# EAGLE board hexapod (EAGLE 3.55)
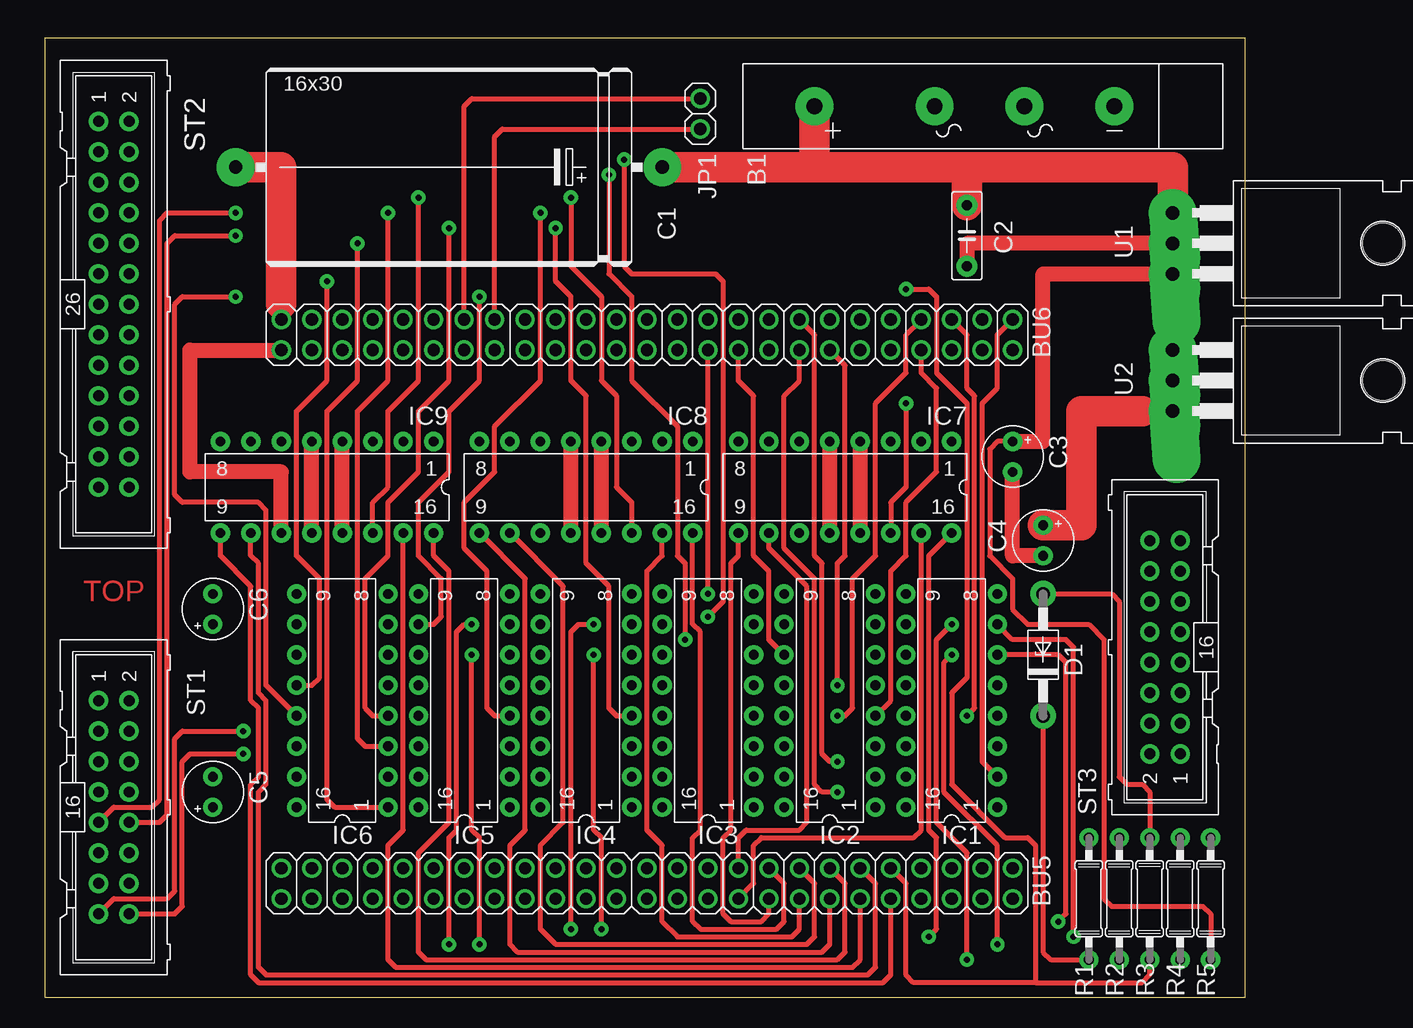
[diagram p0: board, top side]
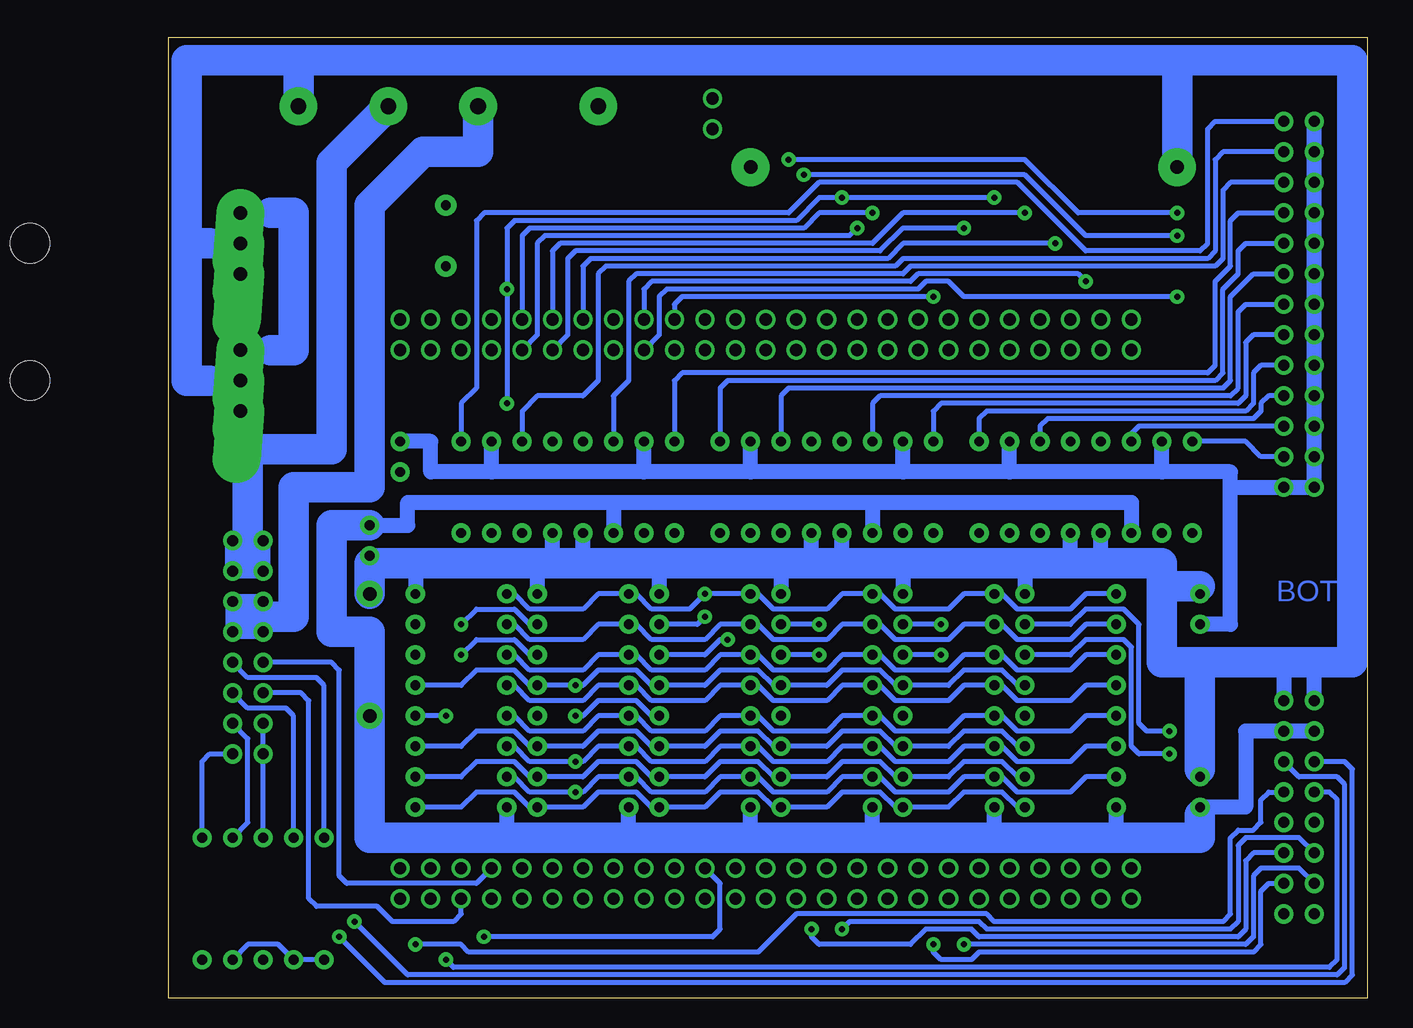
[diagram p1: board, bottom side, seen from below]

Size 100 x 80 mm. Coordinates in mm from the lower left corner, seen from the top.
Outline: 0,0 0,80 100,80 100,0 0,0
Copper layers used: Top, Bottom

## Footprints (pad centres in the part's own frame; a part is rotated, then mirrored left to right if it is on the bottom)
100 = drill 1.321 pad 3.15 round:  0,0;  10.008,0;  17.501,0;  24.994,0
25 = drill 1.016 pad 1.6 round:  -30.48,-1.27;  -30.48,1.27;  -27.94,-1.27;  -27.94,1.27;  -25.4,-1.27;  -25.4,1.27;  -22.86,-1.27;  -22.86,1.27;  -20.32,-1.27;  -20.32,1.27;  -17.78,-1.27;  -17.78,1.27;  -15.24,-1.27;  -15.24,1.27;  -12.7,-1.27;  -12.7,1.27;  -10.16,-1.27;  -10.16,1.27;  -7.62,-1.27;  -7.62,1.27;  -5.08,-1.27;  -5.08,1.27;  -2.54,-1.27;  -2.54,1.27;  0,-1.27;  0,1.27;  2.54,-1.27;  2.54,1.27;  5.08,-1.27;  5.08,1.27;  7.62,-1.27;  7.62,1.27;  10.16,-1.27;  10.16,1.27;  12.7,-1.27;  12.7,1.27;  15.24,-1.27;  15.24,1.27;  17.78,-1.27;  17.78,1.27;  20.32,1.27;  20.32,-1.27;  22.86,-1.27;  25.4,-1.27;  27.94,-1.27;  27.94,1.27;  25.4,1.27;  22.86,1.27;  30.48,1.27;  30.48,-1.27
5-16 = drill 1.118 pad 3.15 round:  -17.78,0;  17.78,0
B2,5A = drill 0.813 pad 1.778 round:  -2.54,0;  2.54,0
,5-5 = drill 0.813 pad 1.6 round:  1.27,0;  -1.27,0
41Z10 = drill 1.118 pad 2.159 round:  -5.08,0;  5.08,0
L-16 = drill 0.813 pad 1.6 round:  -8.89,-3.81;  -6.35,-3.81;  -3.81,-3.81;  -1.27,-3.81;  1.27,-3.81;  3.81,-3.81;  6.35,-3.81;  8.89,-3.81;  8.89,3.81;  6.35,3.81;  3.81,3.81;  1.27,3.81;  -1.27,3.81;  -3.81,3.81;  -6.35,3.81;  -8.89,3.81
02 = drill 1.016 pad 1.6 round:  -1.27,0;  1.27,0
07/10 = drill 0.813 pad 1.6 round:  -5.08,0;  5.08,0
16 = drill 0.914 pad 1.6 round:  -8.89,-1.27;  -8.89,1.27;  -6.35,-1.27;  -6.35,1.27;  -3.81,-1.27;  -3.81,1.27;  -1.27,-1.27;  -1.27,1.27;  1.27,-1.27;  1.27,1.27;  3.81,-1.27;  3.81,1.27;  6.35,-1.27;  6.35,1.27;  8.89,-1.27;  8.89,1.27
26 = drill 0.914 pad 1.6 round:  -15.24,-1.27;  -15.24,1.27;  -12.7,-1.27;  -12.7,1.27;  -10.16,-1.27;  -10.16,1.27;  -7.62,-1.27;  -7.62,1.27;  -5.08,-1.27;  -5.08,1.27;  -2.54,-1.27;  -2.54,1.27;  0,-1.27;  0,1.27;  2.54,-1.27;  2.54,1.27;  5.08,-1.27;  5.08,1.27;  7.62,-1.27;  7.62,1.27;  10.16,-1.27;  10.16,1.27;  12.7,-1.27;  12.7,1.27;  15.24,-1.27;  15.24,1.27
220H = drill 1.118 pad 4 offset:  -2.54,-6.35;  0,-6.35;  2.54,-6.35 | hole 3.302: 0,11.176

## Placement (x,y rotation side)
B1  FB100  [100]  64.14,74.3 0 top
BU5  PINHD-2X25  [25]  50.16,9.53 180 top
BU6  PINHD-2X25  [25]  50.16,55.24 180 top
C1  2200uF/35V  [5-16]  33.66,69.22 180 top
C2  100nf  [B2,5A]  76.83,63.5 90 top
C3  4,7uf/35V  [,5-5]  80.64,45.09 270 top
C4  4,7uf/10V  [,5-5]  83.19,38.1 270 top
C5  4,7uf/10V  [,5-5]  13.97,17.14 90 top
C6  4,7uf/35V  [,5-5]  13.97,32.38 90 top
D1  BZX85  [41Z10]  83.19,28.57 90 top
IC1  HCTL2016  [L-16]  75.56,24.77 90 top
IC2  HCTL2016  [L-16]  65.41,24.77 90 top
IC3  HCTL2016  [L-16]  55.24,24.77 90 top
IC4  HCTL2016  [L-16]  45.09,24.77 90 top
IC5  HCTL2016  [L-16]  34.92,24.77 90 top
IC6  HCTL2016  [L-16]  24.77,24.77 90 top
IC7  DS3668  [L-16]  66.67,42.55 180 top
IC8  DS3668  [L-16]  45.09,42.55 180 top
IC9  DS3668  [L-16]  23.5,42.55 180 top
JP1  PINHD-1X2  [02]  54.61,73.66 270 top
R1  0207/10  [07/10]  87,8.26 90 top
R2  0207/10  [07/10]  89.53,8.26 90 top
R3  10k  [07/10]  92.08,8.26 270 top
R4  0207/10  [07/10]  94.61,8.26 90 top
R5  0207/10  [07/10]  97.16,8.26 90 top
ST1  PINHD-2X8  [16]  5.71,15.88 270 top
ST2  PINHD-2X13  [26]  5.71,57.78 270 top
ST3  PINHD-2X8  [16]  93.34,29.21 90 top
U1  78S24  [220H]  100.33,62.87 270 top
U2  7805  [220H]  100.33,51.44 270 top

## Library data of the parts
B1 = RECTIF
BU5 BU6 JP1 = PINHEAD
C1 C3-C6 = ELKO
C2 = CAP-WI
D1 = diode
IC1-IC9 = klaus
R1-R5 = R
ST1-ST3 = ST-ML
U1 U2 = LINEAR

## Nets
+5V: BU6. C4. C5. D1. IC1. IC2. IC3. IC4. IC5. IC6. IC7. IC8. IC9. R1. R2. R4. ST1. U2.
+24V: C3. C6. IC7. IC8. IC9. R5. ST2. U1.
AC1: B1. ST3.
AC2: B1. ST3.
CLK: BU6. IC1. IC2. IC3. IC4. IC5. IC6.
COIL0: IC7. ST2.
COIL1: IC7. ST2.
COIL2: IC7. ST2.
COIL3: IC7. ST2.
COIL4: IC8. ST2.
COIL5: IC8. ST2.
COIL6: IC8. ST2.
COIL7: IC8. ST2.
COIL8: IC9. ST2.
COIL9: IC9. ST2.
COIL10: IC9. ST2.
COIL11: IC9. ST2.
D0: BU6. IC1. IC2. IC3. IC4. IC5. IC6.
D1: BU6. IC1. IC2. IC3. IC4. IC5. IC6.
D2: BU6. IC1. IC2. IC3. IC4. IC5. IC6.
D3: BU6. IC1. IC2. IC3. IC4. IC5. IC6.
D4: BU6. IC1. IC2. IC3. IC4. IC5. IC6.
D5: BU6. IC1. IC2. IC3. IC4. IC5. IC6.
D6: BU6. IC1. IC2. IC3. IC4. IC5. IC6.
D7: BU6. IC1. IC2. IC3. IC4. IC5. IC6.
EN: BU5. IC7. IC8. IC9. R3.
ENC0: IC1. ST1.
ENC1: IC1. ST1.
ENC2: IC2. ST1.
ENC3: IC2. ST1.
ENC4: IC3. ST1.
ENC5: IC3. ST1.
ENC6: IC4. ST1.
ENC7: IC4. ST1.
ENC8: IC5. ST1.
ENC9: IC5. ST1.
ENC10: IC6. ST1.
ENC11: IC6. ST1.
GND: B1. BU6. C1. C2. C3. C4. C5. C6. D1. IC1. IC2. IC3. IC4. IC5. IC6. IC7. IC8. IC9. R3. ST1. ST3. U1. U2.
N$4: R5. ST3.
N$5: R4. ST3.
N$6: R2. ST3.
N$7: R1. ST3.
N$8: BU6. JP1.
N$9: BU6. JP1.
OE\0: BU6. IC1.
OE\1: BU6. IC2.
OE\2: BU6. IC3.
OE\3: BU6. IC4.
OE\4: BU6. IC5.
OE\5: BU6. IC6.
RST\: BU6. IC1. IC2. IC3. IC4. IC5. IC6.
SEL: BU6. IC1. IC2. IC3. IC4. IC5. IC6.
STATUS0: BU5. ST3.
STATUS1: BU5. ST3.
VALVE0: BU5. IC7.
VALVE1: BU5. IC7.
VALVE2: BU5. IC7.
VALVE3: BU5. IC7.
VALVE4: BU5. IC8.
VALVE5: BU5. IC8.
VALVE6: BU5. IC8.
VALVE7: BU5. IC8.
VALVE8: BU5. IC9.
VALVE9: BU5. IC9.
VALVE10: BU5. IC9.
VALVE11: BU5. IC9.
VIN: B1. C1. C2. U1. U2.

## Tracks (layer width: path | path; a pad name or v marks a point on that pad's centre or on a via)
+5V
  Top 0.406: 87,3.17 83.82,3.17 83.19,3.81 83.19,23.5
  Top 1.27: 19.68,53.98 12.06,53.98 12.06,43.81 19.68,43.81 19.68,38.73 | 91.44,48.9 U2.
  Top 2.54: C4. 86.36,39.37 86.36,48.9 91.44,48.9
  Bottom 0.406: 87,3.17 89.53,3.17 90.81,4.45 93.34,4.45 94.61,3.17
  Bottom 1.27: 20.95,13.34 IC6. | 31.11,13.34 IC5. | 41.27,13.34 IC4. | 51.44,13.34 IC3. | 61.59,13.34 IC2. | 71.75,13.34 IC1. | 19.68,38.73 19.68,41.27 41.27,41.27 | 62.87,41.27 41.27,41.27 | 41.27,41.27 41.27,38.73 | 62.87,41.27 62.87,38.73 | 62.87,41.27 80.01,41.27 80.01,39.37 C4. | 13.97,15.24 C5. 10.16,15.88 10.16,22.23 6.99,22.23 4.45,22.23
  Bottom 2.54: C4. 86.36,39.37 86.36,30.48 83.19,30.48 83.19,23.5 83.19,13.34 71.75,13.34 61.59,13.34 51.44,13.34 41.27,13.34 31.11,13.34 20.95,13.34 13.97,13.34 13.97,15.24
+24V
  Top 0.406: 97.16,3.17 97.16,6.99 96.52,7.62 88.9,7.62 88.27,8.26 88.27,29.84 87,31.11 81.92,31.11 80.64,32.38 80.64,34.92 78.74,36.83 78.74,45.72 79.38,46.35 C3.
  Top 1.27: C3. 83.19,46.35 83.19,60.33 U1.
  Bottom 1.27: 17.14,43.81 17.14,46.35 | C3. 78.11,46.35 78.11,43.81 73.03,43.81 | 60.33,43.81 73.03,43.81 | 51.44,43.81 60.33,43.81 | 38.73,43.81 51.44,43.81 | 29.84,43.81 38.73,43.81 | 17.14,43.81 29.84,43.81 | 29.84,43.81 29.84,46.35 | 38.73,43.81 38.73,46.35 | 51.44,43.81 51.44,46.35 | 60.33,43.81 60.33,46.35 | 73.03,43.81 73.03,46.35 | 17.14,43.81 11.43,43.81 11.43,42.55 | 11.43,42.55 ST2. 4.45,42.55 4.45,45.09 4.45,47.62 4.45,50.16 4.45,52.7 4.45,55.24 4.45,57.78 4.45,60.33 4.45,62.87 4.45,65.41 4.45,67.94 4.45,70.48 4.45,73.03 | 11.43,42.55 11.43,31.11 C6.
AC1
  Bottom 1.27: 92.08,30.48 94.61,30.48 94.61,33.02 92.08,33.02 92.08,31.75 92.08,30.48
  Bottom 1.524: 92.08,30.48 94.61,33.02 | 92.08,33.02 94.61,30.48
  Bottom 2.54: 74.14,74.3 74.14,70.48 78.74,70.48 83.19,66.04 83.19,42.55 89.53,42.55 89.53,31.75 92.08,31.75
AC2
  Bottom 1.27: 92.08,35.56 94.61,35.56 94.61,38.1 93.34,38.1 ST3. 92.08,35.56
  Bottom 1.524: 92.08,35.56 94.61,38.1 | 94.61,35.56 ST3.
  Bottom 2.54: 93.34,38.1 93.34,45.72 86.36,45.72 86.36,69.57 81.64,74.3
CLK
  Top 0.406: 79.38,18.41 78.11,19.68 78.11,49.53 79.38,50.8 79.38,55.24 80.64,56.52
  Bottom 0.406: 28.57,18.41 29.21,18.41 30.48,19.68 33.66,19.68 34.92,18.41 38.73,18.41 39.37,18.41 40.64,19.68 43.81,19.68 45.09,18.41 48.9,18.41 49.53,18.41 50.8,19.68 53.98,19.68 55.24,18.41 59.05,18.41 59.69,18.41 60.96,19.68 64.14,19.68 65.41,18.41 69.22,18.41 69.85,18.41 71.12,19.68 74.3,19.68 75.56,18.41 79.38,18.41
COIL0
  Bottom 0.406: 75.56,46.35 75.56,49.53 74.3,50.8 74.3,64.77 73.66,65.41 48.26,65.41 45.72,67.94 29.21,67.94 23.5,62.23 13.97,62.23 13.34,62.87 13.34,72.39 12.7,73.03 6.99,73.03
COIL1
  Bottom 0.406: 70.48,46.35 70.48,48.9 69.22,50.16 65.41,50.16 64.14,51.44 64.14,60.33 63.5,60.96 39.37,60.96 38.73,61.59 13.34,61.59 12.7,62.23 12.7,69.85 12.06,70.48 6.99,70.48
COIL2
  Bottom 0.406: 62.87,46.35 62.87,50.16 61.59,51.44 61.59,59.69 60.96,60.33 38.73,60.33 38.1,60.96 12.7,60.96 12.06,61.59 12.06,67.31 11.43,67.94 6.99,67.94
COIL3
  Bottom 0.406: 6.99,65.41 10.79,65.41 11.43,64.77 11.43,60.96 12.7,59.69 12.7,52.7 13.34,52.07 57.15,52.07 57.78,51.44 57.78,46.35
COIL4
  Bottom 0.406: 6.99,62.87 10.16,62.87 10.79,62.23 10.79,60.33 12.06,59.05 12.06,52.07 12.7,51.44 53.34,51.44 53.98,50.8 53.98,46.35
COIL5
  Bottom 0.406: 6.99,60.33 9.53,60.33 11.43,58.42 11.43,51.44 12.06,50.8 48.26,50.8 48.9,50.16 48.9,46.35
COIL6
  Bottom 0.406: 41.27,46.35 41.27,49.53 40.64,50.16 11.43,50.16 10.79,50.8 10.79,57.15 10.16,57.78 6.99,57.78
COIL7
  Bottom 0.406: 36.2,46.35 36.2,48.9 35.56,49.53 10.79,49.53 10.16,50.16 10.16,54.61 9.53,55.24 6.99,55.24
COIL8
  Bottom 0.406: 32.38,46.35 32.38,48.26 31.75,48.9 10.16,48.9 9.53,49.53 9.53,52.07 8.89,52.7 6.99,52.7
COIL9
  Bottom 0.406: 27.3,46.35 27.3,47.62 26.67,48.26 9.53,48.26 8.89,48.9 8.89,49.53 8.26,50.16 6.99,50.16
COIL10
  Bottom 0.406: 19.68,46.35 19.68,46.99 19.05,47.62 6.99,47.62
COIL11
  Bottom 0.406: 6.99,45.09 8.89,45.09 10.16,46.35 14.61,46.35
D0  (via drill 0.5 pad 1.2)
  Top 0.406: 28.57,15.88 24.13,15.88 23.5,16.51 23.5,48.9 26.04,51.44 v26.04,62.87
  Bottom 0.406: 28.57,15.88 29.21,15.88 30.48,17.14 33.66,17.14 34.92,15.88 38.73,15.88 39.37,15.88 40.64,17.14 43.81,17.14 45.09,15.88 48.9,15.88 49.53,15.88 50.8,17.14 53.98,17.14 55.24,15.88 59.05,15.88 59.69,15.88 60.96,17.14 64.14,17.14 65.41,15.88 69.22,15.88 69.85,15.88 71.12,17.14 74.3,17.14 75.56,15.88 79.38,15.88 | 65.41,56.52 65.41,60.96 64.77,61.59 40.01,61.59 38.73,62.87 v26.04,62.87
D1  (via drill 0.5 pad 1.2)
  Top 0.406: 62.87,53.98 62.87,51.44 61.59,50.16 61.59,37.47 64.14,34.92 64.14,17.78 64.77,17.14 v66.04,17.14
  Bottom 0.406: 20.95,18.41 23.5,18.41 24.77,17.14 29.21,17.14 30.48,18.41 31.11,18.41 33.66,18.41 34.92,17.14 39.37,17.14 40.64,18.41 41.27,18.41 43.81,18.41 45.09,17.14 49.53,17.14 50.8,18.41 51.44,18.41 53.98,18.41 55.24,17.14 59.69,17.14 60.96,18.41 61.59,18.41 64.14,18.41 65.41,17.14 v66.04,17.14 69.85,17.14 71.12,18.41 71.75,18.41
D2  (via drill 0.5 pad 1.2)
  Top 0.406: 62.87,56.52 64.14,55.24 64.14,36.83 64.77,36.2 64.77,20.32 65.41,19.68 v66.04,19.68
  Bottom 0.406: 20.95,20.95 23.5,20.95 24.77,19.68 29.21,19.68 30.48,20.95 31.11,20.95 33.66,20.95 34.92,19.68 39.37,19.68 40.64,20.95 41.27,20.95 43.81,20.95 45.09,19.68 49.53,19.68 50.8,20.95 51.44,20.95 53.98,20.95 55.24,19.68 59.69,19.68 60.96,20.95 61.59,20.95 64.14,20.95 65.41,19.68 v66.04,19.68 69.85,19.68 71.12,20.95 71.75,20.95
D3  (via drill 0.5 pad 1.2)
  Top 0.406: 20.95,23.5 18.41,26.04 18.41,40.64 17.78,41.27 11.43,41.27 10.79,41.91 10.79,57.78 11.43,58.42 v15.88,58.42
  Bottom 0.406: 20.95,23.5 23.5,23.5 24.77,22.23 29.21,22.23 30.48,23.5 31.11,23.5 33.66,23.5 34.92,22.23 39.37,22.23 40.64,23.5 41.27,23.5 43.81,23.5 45.09,22.23 49.53,22.23 50.8,23.5 51.44,23.5 53.98,23.5 55.24,22.23 59.69,22.23 60.96,23.5 61.59,23.5 64.14,23.5 65.41,22.23 69.85,22.23 71.12,23.5 71.75,23.5 | 60.33,53.98 59.05,55.24 59.05,58.42 58.42,59.05 37.47,59.05 36.83,59.69 34.92,59.69 33.66,58.42 v15.88,58.42
D4  (via drill 0.5 pad 1.2)
  Top 0.406: 20.95,26.04 22.23,26.04 22.86,26.67 22.86,34.92 20.95,36.83 20.95,48.9 23.5,51.44 v23.5,59.69
  Bottom 0.406: 20.95,26.04 23.5,26.04 24.77,24.77 29.21,24.77 30.48,26.04 31.11,26.04 33.66,26.04 34.92,24.77 39.37,24.77 40.64,26.04 41.27,26.04 43.81,26.04 45.09,24.77 49.53,24.77 50.8,26.04 51.44,26.04 53.98,26.04 55.24,24.77 59.69,24.77 60.96,26.04 61.59,26.04 64.14,26.04 65.41,24.77 69.85,24.77 71.12,26.04 71.75,26.04 | 60.33,56.52 60.33,59.05 59.69,59.69 38.1,59.69 37.47,60.33 24.13,60.33 v23.5,59.69
D5
  Top 0.406: 57.78,53.98 57.78,51.44 59.05,50.16 59.05,36.83 60.33,35.56 60.33,29.84 61.59,28.57
  Bottom 0.406: 20.95,28.57 23.5,28.57 24.77,27.3 29.21,27.3 30.48,28.57 31.11,28.57 33.66,28.57 34.92,27.3 39.37,27.3 40.64,28.57 41.27,28.57 43.81,28.57 45.09,27.3 49.53,27.3 50.8,28.57 51.44,28.57 53.98,28.57 55.24,27.3 59.69,27.3 60.96,28.57 61.59,28.57 64.14,28.57 65.41,27.3 69.85,27.3 71.12,28.57 71.75,28.57
D6  (via drill 0.5 pad 1.2)
  Top 0.406: 31.11,31.11 32.38,31.11 33.02,31.75 33.02,34.92 31.11,36.83 31.11,41.27 33.66,43.81 33.66,48.9 36.2,51.44 v36.2,58.42
  Bottom 0.406: 20.95,31.11 23.5,31.11 24.77,29.84 29.21,29.84 30.48,31.11 31.11,31.11 33.66,31.11 34.92,29.84 39.37,29.84 40.64,31.11 41.27,31.11 43.81,31.11 45.09,29.84 49.53,29.84 50.8,31.11 51.44,31.11 53.98,31.11 55.24,29.84 59.69,29.84 60.96,31.11 61.59,31.11 64.14,31.11 65.41,29.84 69.85,29.84 71.12,31.11 71.75,31.11 | 57.78,56.52 57.78,57.78 57.15,58.42 v36.2,58.42
D7  (via drill 0.5 pad 1.2)
  Top 0.406: v55.24,33.66 55.24,53.98
  Bottom 0.406: 20.95,33.66 23.5,33.66 24.77,32.38 29.21,32.38 30.48,33.66 31.11,33.66 33.66,33.66 34.92,32.38 39.37,32.38 40.64,33.66 41.27,33.66 43.81,33.66 45.09,32.38 49.53,32.38 50.8,33.66 51.44,33.66 v55.24,33.66 56.52,32.38 59.69,32.38 60.96,33.66 61.59,33.66 64.14,33.66 65.41,32.38 69.85,32.38 71.12,33.66 71.75,33.66
EN  (via drill 0.5 pad 1.2)
  Top 0.406: 27.3,38.73 27.3,41.27 28.57,42.55 28.57,48.9 31.11,51.44 v31.11,66.67 | 48.9,38.73 48.9,41.27 47.62,42.55 47.62,50.16 46.35,51.44 46.35,58.42 43.81,60.96 v43.81,66.67 | 70.48,38.73 70.48,41.27 71.75,42.55 v71.75,49.53 | 70.48,10.79 71.75,9.53 71.75,1.91 72.39,1.27 82.55,1.27 | 82.55,1.27 91.44,1.27 92.08,1.91 R3. | v71.75,59.05 73.66,59.05 74.3,58.42 74.3,52.07 76.83,49.53 76.83,26.67 75.56,25.4 75.56,17.78 80.01,13.34 81.92,13.34 82.55,12.7 82.55,1.27
  Bottom 0.406: v71.75,49.53 v71.75,59.05 71.75,64.14 71.12,64.77 47.62,64.77 45.72,66.67 v43.81,66.67 v31.11,66.67
ENC0  (via drill 0.5 pad 1.2)
  Top 0.406: v85.72,5.08 85.72,29.21 85.09,29.84 80.64,29.84 79.38,31.11
  Bottom 0.406: v85.72,5.08 81.92,1.27 1.91,1.27 1.27,1.91 1.27,19.05 1.91,19.68 4.45,19.68
ENC1  (via drill 0.5 pad 1.2)
  Top 0.406: 79.38,28.57 84.45,28.57 85.09,27.94 85.09,6.99 v84.45,6.35
  Bottom 0.406: v84.45,6.35 80.01,1.91 2.54,1.91 1.91,2.54 1.91,17.78 2.54,18.41 5.71,18.41 6.99,19.68
ENC2  (via drill 0.5 pad 1.2)
  Top 0.406: v75.56,31.11 74.3,29.84 74.3,14.61 76.83,12.06 v76.83,3.17
  Bottom 0.406: 69.22,31.11 69.85,31.11 71.12,32.38 74.3,32.38 v75.56,31.11 | v76.83,3.17 76.2,2.54 3.17,2.54 2.54,3.17 2.54,16.51 3.17,17.14 4.45,17.14
ENC3  (via drill 0.5 pad 1.2)
  Top 0.406: v75.56,28.57 74.93,27.94 74.93,17.14 79.38,12.7 v79.38,4.45
  Bottom 0.406: 69.22,28.57 69.85,28.57 71.12,29.84 74.3,29.84 v75.56,28.57 | v79.38,4.45 75.56,4.45 74.93,3.81 50.8,3.81 47.62,6.99 31.75,6.99 31.11,6.35 12.06,6.35 11.43,6.99 11.43,13.34 10.79,13.97 9.53,13.97 8.89,14.61 8.89,16.51 8.26,17.14 6.99,17.14
ENC4  (via drill 0.5 pad 1.2)
  Top 0.406: v55.24,31.75 56.52,33.02 56.52,59.69 55.88,60.33 48.9,60.33 48.26,60.96 v48.26,69.85 | v15.88,65.41 10.16,65.41 9.53,64.77 9.53,16.51 8.89,15.88 5.71,15.88 4.45,14.61
  Bottom 0.406: 59.05,31.11 55.88,31.11 v55.24,31.75 | v15.88,65.41 24.13,65.41 28.57,69.85 v48.26,69.85
ENC5  (via drill 0.5 pad 1.2)
  Top 0.406: v15.88,63.5 10.79,63.5 10.16,62.87 10.16,15.24 9.53,14.61 6.99,14.61 | v46.99,68.58 46.99,60.33 48.9,58.42 48.9,51.44 52.7,47.62 52.7,36.83 53.34,36.2 v53.34,29.84
  Bottom 0.406: v15.88,63.5 23.5,63.5 28.57,68.58 v46.99,68.58 | 59.05,28.57 55.24,28.57 53.98,29.84 v53.34,29.84
ENC6  (via drill 0.5 pad 1.2)
  Top 0.406: v45.72,31.11 44.45,31.11 43.81,30.48 v43.81,5.71
  Bottom 0.406: v45.72,31.11 48.9,31.11 | v43.81,5.71 43.18,6.35 32.38,6.35 31.75,5.71 11.43,5.71 10.79,6.35 10.79,12.7 10.16,13.34 5.71,13.34 4.45,12.06
ENC7  (via drill 0.5 pad 1.2)
  Top 0.406: v46.35,5.71 46.35,13.34 45.72,13.97 v45.72,28.57
  Bottom 0.406: v45.72,28.57 48.9,28.57 | v46.35,5.71 46.35,5.08 45.72,4.45 38.1,4.45 36.83,5.71 33.02,5.71 32.38,5.08 10.79,5.08 10.16,5.71 10.16,11.43 9.53,12.06 6.99,12.06
ENC8  (via drill 0.5 pad 1.2)
  Top 0.406: v35.56,31.11 34.92,31.11 34.29,30.48 34.29,13.97 33.66,13.34 v33.66,4.45
  Bottom 0.406: v35.56,31.11 38.73,31.11 | v33.66,4.45 10.16,4.45 9.53,5.08 9.53,10.16 8.89,10.79 5.71,10.79 4.45,9.53
ENC9  (via drill 0.5 pad 1.2)
  Top 0.406: v36.2,4.45 36.2,13.34 35.56,13.97 v35.56,28.57
  Bottom 0.406: v35.56,28.57 38.73,28.57 | v36.2,4.45 36.2,3.81 35.56,3.17 33.02,3.17 32.38,3.81 9.53,3.81 8.89,4.45 8.89,8.89 8.26,9.53 6.99,9.53
ENC10  (via drill 0.5 pad 1.2)
  Top 0.406: v16.51,22.23 11.43,22.23 10.79,21.59 10.79,8.89 10.16,8.26 5.71,8.26 4.45,6.99
  Bottom 0.406: 28.57,31.11 24.77,31.11 23.5,32.38 20.32,32.38 19.05,31.11 19.05,22.86 18.41,22.23 v16.51,22.23
ENC11  (via drill 0.5 pad 1.2)
  Top 0.406: v16.51,20.32 12.06,20.32 11.43,19.68 11.43,7.62 10.79,6.99 ST1.
  Bottom 0.406: 28.57,28.57 24.77,28.57 23.5,29.84 20.32,29.84 19.68,29.21 19.68,20.95 19.05,20.32 v16.51,20.32
GND
  Top 0.406: 92.08,13.34 92.08,17.14 91.44,17.78 90.17,17.78 89.53,18.41 89.53,33.02 88.9,33.66 D1.
  Top 1.27: 22.23,38.73 22.23,46.35 | 43.81,38.73 43.81,46.35 | 65.41,38.73 65.41,46.35 | 24.77,38.73 24.77,46.35 | 46.35,38.73 46.35,46.35 | 67.94,38.73 67.94,46.35 | 19.68,57.78 BU6. | 76.83,60.96 76.83,62.87 93.98,62.87 | 80.64,43.81 80.64,36.83 83.19,36.83
  Top 2.54: C1. 19.68,69.22 19.68,57.78
  Bottom 0.406: 92.08,22.86 92.08,20.32 92.08,13.34
  Bottom 1.27: 28.57,36.2 28.57,33.66 | 38.73,36.2 38.73,33.66 | 48.9,36.2 48.9,33.66 | 59.05,36.2 59.05,33.66 | 69.22,36.2 69.22,33.66 | 79.38,36.2 79.38,33.66 | 67.94,36.2 67.94,38.73 | 46.35,36.2 46.35,38.73 | 24.77,36.2 24.77,38.73 | 22.23,36.2 22.23,38.73 | 43.81,36.2 43.81,38.73 | 65.41,36.2 65.41,38.73 | 13.97,19.05 13.97,18.41 | 13.97,34.29 13.97,33.66 | 83.19,36.2 83.19,36.83 | 96.52,62.87 93.98,62.87 | 96.52,51.44 93.98,51.44 | 4.45,24.77 4.45,27.94 | 6.99,27.94 6.99,24.77
  Bottom 2.54: 15.88,78.11 C1. | 13.97,19.05 13.97,24.77 13.97,27.94 | D1. 83.19,36.2 79.38,36.2 69.22,36.2 67.94,36.2 65.41,36.2 59.05,36.2 48.9,36.2 46.35,36.2 43.81,36.2 38.73,36.2 28.57,36.2 24.77,36.2 22.23,36.2 17.14,36.2 17.14,34.29 | 17.14,34.29 17.14,27.94 13.97,27.94 | 17.14,34.29 13.97,34.29 | B1. 89.13,78.11 88.9,78.11 | 15.88,78.11 88.9,78.11 | 98.42,62.87 98.42,51.44 96.52,51.44 | 98.42,62.87 96.52,62.87 | 88.9,78.11 98.42,78.11 98.42,62.87 | 15.88,78.11 1.27,78.11 1.27,27.94 4.45,27.94 6.99,27.94 13.97,27.94
N$4
  Bottom 0.406: 94.61,20.32 96.52,20.32 97.16,19.68 R5.
N$5
  Bottom 0.406: 94.61,22.86 93.34,21.59 93.34,14.61 R4.
N$6
  Bottom 0.406: 94.61,25.4 93.34,24.13 90.17,24.13 89.53,23.5 R2.
N$7
  Bottom 0.406: 94.61,27.94 93.34,26.67 87.63,26.67 87,26.04 R1.
N$8
  Top 0.406: 37.47,56.52 37.47,71.75 38.1,72.39 JP1.
N$9
  Top 0.406: 34.92,56.52 34.92,74.3 35.56,74.93 54.61,74.93
OE\0  (via drill 0.5 pad 1.2)
  Top 0.406: 75.56,56.52 76.83,55.24 76.83,50.8 77.47,50.16 77.47,24.13 v76.83,23.5
  Bottom 0.406: v76.83,23.5 79.38,23.5
OE\1
  Top 0.406: 69.22,23.5 70.48,24.77 70.48,35.56 71.75,36.83 71.75,41.27 74.3,43.81 74.3,50.8 73.03,52.07 73.03,53.98
OE\2  (via drill 0.5 pad 1.2)
  Top 0.406: v66.04,23.5 66.67,23.5 67.31,24.13 67.31,34.92 69.22,36.83 69.22,49.53 71.75,52.07 71.75,55.24 73.03,56.52
  Bottom 0.406: 59.05,23.5 59.69,23.5 60.96,24.77 64.14,24.77 65.41,23.5 v66.04,23.5
OE\3  (via drill 0.5 pad 1.2)
  Top 0.406: 48.9,23.5 47.62,23.5 46.99,24.13 46.99,34.29 45.09,36.2 45.09,50.16 43.81,51.44 43.81,58.42 42.55,59.69 v42.55,64.14
  Bottom 0.406: 70.48,53.98 69.22,55.24 69.22,62.87 68.58,63.5 43.18,63.5 v42.55,64.14
OE\4  (via drill 0.5 pad 1.2)
  Top 0.406: 38.73,23.5 37.47,23.5 36.83,24.13 36.83,35.56 34.92,37.47 34.92,41.27 37.47,43.81 37.47,47.62 41.27,51.44 v41.27,65.41
  Bottom 0.406: 70.48,56.52 70.48,63.5 69.85,64.14 46.99,64.14 45.72,65.41 v41.27,65.41
OE\5  (via drill 0.5 pad 1.2)
  Top 0.406: 28.57,23.5 27.3,23.5 26.67,24.13 26.67,34.92 28.57,36.83 28.57,41.27 31.11,43.81 31.11,48.9 33.66,51.44 v33.66,64.14
  Bottom 0.406: 67.94,53.98 66.67,55.24 66.67,61.59 66.04,62.23 40.64,62.23 38.73,64.14 v33.66,64.14
RST\  (via drill 0.5 pad 1.2)
  Top 0.406: 65.41,53.98 66.67,52.7 66.67,36.83 66.04,36.2 v66.04,26.04
  Bottom 0.406: 28.57,26.04 29.21,26.04 30.48,27.3 33.66,27.3 34.92,26.04 38.73,26.04 39.37,26.04 40.64,27.3 43.81,27.3 45.09,26.04 48.9,26.04 49.53,26.04 50.8,27.3 53.98,27.3 55.24,26.04 59.05,26.04 59.69,26.04 60.96,27.3 64.14,27.3 65.41,26.04 v66.04,26.04 69.22,26.04 69.85,26.04 71.12,27.3 74.3,27.3 75.56,26.04 79.38,26.04
SEL  (via drill 0.5 pad 1.2)
  Top 0.406: 28.57,20.95 26.67,20.95 26.04,21.59 26.04,48.9 28.57,51.44 v28.57,65.41
  Bottom 0.406: 28.57,20.95 29.21,20.95 30.48,22.23 33.66,22.23 34.92,20.95 38.73,20.95 39.37,20.95 40.64,22.23 43.81,22.23 45.09,20.95 48.9,20.95 49.53,20.95 50.8,22.23 53.98,22.23 55.24,20.95 59.05,20.95 59.69,20.95 60.96,22.23 64.14,22.23 65.41,20.95 69.22,20.95 69.85,20.95 71.12,22.23 74.3,22.23 75.56,20.95 79.38,20.95 | 67.94,56.52 67.94,62.23 67.31,62.87 41.27,62.87 38.73,65.41 v28.57,65.41
STATUS0
  Bottom 0.406: 92.08,27.94 86.36,27.94 85.72,27.3 85.72,10.16 85.09,9.53 74.3,9.53 73.03,10.79
STATUS1
  Bottom 0.406: 92.08,25.4 88.9,25.4 88.27,24.77 88.27,8.26 87.63,7.62 82.55,7.62 81.28,6.35 76.2,6.35 75.56,6.99 75.56,8.26
VALVE0  (via drill 0.5 pad 1.2)
  Top 0.406: IC7. 73.66,36.83 73.66,13.97 74.3,13.34 74.3,5.71 v73.66,5.08
  Bottom 0.406: 55.24,10.79 53.98,9.53 53.98,5.71 54.61,5.08 v73.66,5.08
VALVE1
  Top 0.406: 73.03,38.73 73.03,13.97 72.39,13.34 59.69,13.34 59.05,12.7 59.05,9.53 57.78,8.26
VALVE2
  Top 0.406: 57.78,10.79 57.78,13.34 58.42,13.97 62.87,13.97 63.5,14.61 63.5,34.29 60.33,37.47 60.33,38.73
VALVE3
  Top 0.406: 57.78,38.73 57.78,36.83 57.15,36.2 57.15,13.97 56.52,13.34 56.52,6.99 57.15,6.35 59.69,6.35 60.33,6.99 60.33,8.26
VALVE4
  Top 0.406: IC8. 53.98,31.11 54.61,30.48 54.61,13.97 53.98,13.34 53.98,6.35 54.61,5.71 60.96,5.71 61.59,6.35 61.59,9.53 60.33,10.79
VALVE5
  Top 0.406: 51.44,38.73 51.44,36.83 50.16,35.56 50.16,13.97 51.44,12.7 51.44,6.35 52.7,5.08 62.23,5.08 62.87,5.71 62.87,8.26
VALVE6
  Top 0.406: 62.87,10.79 64.14,9.53 64.14,5.08 63.5,4.45 42.55,4.45 41.27,5.71 41.27,12.7 43.18,14.61 43.18,34.29 38.73,38.73
VALVE7
  Top 0.406: 36.2,38.73 40.01,34.92 40.01,13.97 38.73,12.7 38.73,4.45 39.37,3.81 64.77,3.81 65.41,4.45 65.41,8.26
VALVE8
  Top 0.406: IC9. 32.38,36.83 33.66,35.56 33.66,14.61 31.11,12.06 31.11,3.81 31.75,3.17 66.04,3.17 66.67,3.81 66.67,9.53 65.41,10.79
VALVE9
  Top 0.406: 29.84,38.73 29.84,13.97 28.57,12.7 28.57,3.17 29.21,2.54 67.31,2.54 67.94,3.17 67.94,8.26
VALVE10
  Top 0.406: 17.14,38.73 17.14,36.83 17.78,36.2 17.78,25.4 18.41,24.77 18.41,17.78 17.78,17.14 17.78,2.54 18.41,1.91 68.58,1.91 69.22,2.54 69.22,9.53 67.94,10.79
VALVE11
  Top 0.406: 14.61,38.73 14.61,36.83 17.14,34.29 17.14,24.77 17.78,24.13 17.78,18.41 17.14,17.78 17.14,1.91 17.78,1.27 69.85,1.27 70.48,1.91 70.48,8.26
VIN
  Top 1.27: 93.98,66.67 93.98,65.41
  Top 2.54: 51.44,69.22 64.14,69.22 | 64.14,69.22 64.14,74.3 | 64.14,69.22 77.47,69.22 | 77.47,69.22 93.98,69.22 93.98,66.67 | 77.47,69.22 76.83,69.22 C2.
  Bottom 1.27: 91.44,53.98 93.98,53.98 | 93.98,65.41 91.44,65.41
  Bottom 2.54: 91.44,53.98 89.53,53.98 89.53,65.41 91.44,65.41

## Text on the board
Top: TOP
Bottom: BOT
